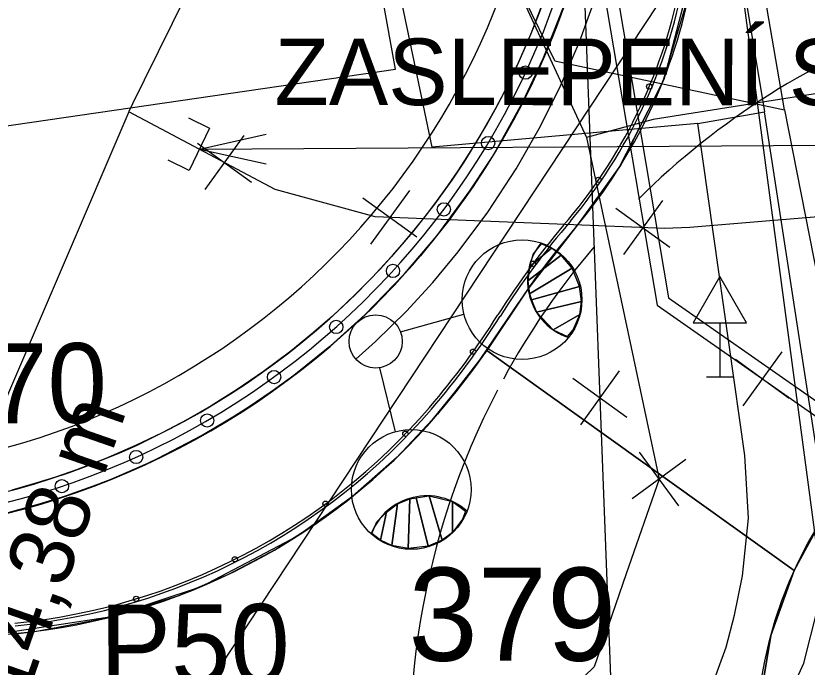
# Model space of a CAD drawing. Extents: x -643342 to -638635, y -1201752 to -1189948.
# Drawn here: x -639514.49 to -639499.63, y -1192712.17 to -1192699.92 of the extents above; entities that cross this region are included whole.
import ezdxf

# ---------------------------------------------------------------- set-up
doc = ezdxf.new("R2010")
doc.units = 0
for name, color, linetype in [('-zbytky_kruháče', 7, 'Continuous'), ('42', 7, 'Continuous'), ('IS_PLYN_STL', 7, 'Continuous'), ('IS_TELEF_MISTNI_ZAMERENO', 7, 'Continuous'), ('IS_VODOVOD_VAS', 7, 'Continuous'), ('IS_VODOVOD_ZRUSENY', 7, 'Continuous'), ('K-HRANICE_KN', 7, 'Continuous'), ('K-ČÍSLA_PARCEL', 7, 'Continuous'), ('kanalizace_dešťová_stávající', 7, 'Continuous'), ('N-CHODNIK', 7, 'Continuous'), ('N-KAN_DEST_TRASA-NÁVRH', 7, 'Continuous'), ('N-OBVOD STAVBY 06', 7, 'Continuous'), ('N-oploceni', 7, 'Continuous'), ('N-rusene_vedeni', 7, 'Continuous'), ('N-SILNICE', 7, 'Continuous'), ('N-SRAFY_PLOCHY', 7, 'Continuous'), ('N-vo', 7, 'Continuous'), ('N-ZDI', 7, 'Continuous'), ('N-úprava plochu u obecního úřadu', 7, 'Continuous'), ('RWE_STL_RADY', 7, 'Continuous'), ('tomaštík - Džuganovi - Vrstva 36', 7, 'Continuous'), ('Vrstva 13', 7, 'Continuous'), ('Vrstva 42', 7, 'Continuous'), ('Vrstva 46', 7, 'Continuous'), ('Z-hrany_a_čáry', 7, 'Continuous'), ('Z-značky', 7, 'Continuous')]:
    doc.layers.add(name, color=color, linetype=linetype)

# ---------------------------------------------------------------- blocks, each defined once
blk = doc.blocks.new('SZASL')
at = {"layer": 'Vrstva 13'}
for p, q in [((-44.1, 44.1), (0, 44.1)), ((0, 44.1), (0, -44.1)), ((0, -44.1), (-44.1, -44.1))]:
    blk.add_line(p, q, dxfattribs=at)
blk = doc.blocks.new('SLOUPEK')
blk.add_circle((0, 0), 0.125)
blk = doc.blocks.new('zs')
at = {"layer": 'N-oploceni'}
blk.add_circle((0, 0), 0.05, dxfattribs=at)

msp = doc.modelspace()

# ---------------------------------------------------------------- linework, layer by layer
at = {"layer": '-zbytky_kruháče'}
for start, end in [(109.782, 134.7666), (139.621, 151.5281), (152.4602, 296.3322)]:
    msp.add_arc((-639492.588, -1192713.663), 14.5, start, end, dxfattribs=at)
at = {"layer": '42'}
msp.add_line((-639511.045, -1192702.433), (-639465.369, -1192702.13), dxfattribs=at)
at = {"layer": 'IS_PLYN_STL'}
for points in [[(-639512.56, -1192644.42), (-639512.26, -1192649.59), (-639511.32, -1192655.27), (-639510.7, -1192659.4), (-639510.65, -1192659.78), (-639509.28, -1192668.1), (-639508.19, -1192675.05), (-639508.14, -1192676.33), (-639508.13, -1192676.63), (-639507.89, -1192680.08), (-639507.71, -1192681.06), (-639506.97, -1192684.98), (-639506.93, -1192686.16), (-639507.42, -1192689.07), (-639507.53, -1192689.98), (-639508.21, -1192692.47), (-639508.65, -1192694.18), (-639512.08, -1192701.13)], [(-639512.08, -1192701.13), (-639512.3, -1192701.58), (-639512.37, -1192701.72), (-639512.37, -1192701.73)], [(-639512.37, -1192701.73), (-639516.15, -1192710.55), (-639516.26, -1192710.8), (-639516.59, -1192711.63), (-639520.92, -1192722.11)], [(-639470.24, -1192716.66), (-639471.45, -1192716.75), (-639474.85, -1192717.23), (-639477.45, -1192717.59), (-639486.49, -1192709.11), (-639487.46, -1192707.33), (-639488.82, -1192705.38), (-639489.11, -1192702.85), (-639489.56, -1192702.88), (-639501.83, -1192703.9), (-639502.31, -1192703.92), (-639507.74, -1192703.7), (-639509.62, -1192703.19), (-639512.37, -1192701.73)]]:
    msp.add_lwpolyline(points, dxfattribs=at)
at = {"layer": 'IS_TELEF_MISTNI_ZAMERENO'}
for p, q in [((-639505.51, -1192698.45), (-639503.77, -1192702.21)), ((-639491.24, -1192700.09), (-639502.52, -1192701.87)), ((-639491.24, -1192700.09), (-639502.52, -1192701.87)), ((-639502.52, -1192701.87), (-639503.77, -1192702.21)), ((-639503.77, -1192702.21), (-639502.41, -1192708.63)), ((-639502.41, -1192708.63), (-639503.03, -1192710.41)), ((-639503.03, -1192710.41), (-639503.63, -1192712.16)), ((-639503.63, -1192712.16), (-639504.73, -1192713.21))]:
    msp.add_line(p, q, dxfattribs=at)
at = {"layer": 'IS_VODOVOD_VAS'}
for points in [[(-639513.05, -1192632.38), (-639511.6, -1192653.11), (-639509.94, -1192661.802), (-639509.17, -1192665.92), (-639508.128, -1192674.317), (-639507.037, -1192678.26), (-639504.087, -1192695.682), (-639502.448, -1192705.362), (-639494.166, -1192711.159), (-639494.54, -1192716.007), (-639495.94, -1192729.045), (-639496.55, -1192731.72), (-639496.617, -1192732.012), (-639498.895, -1192762.442), (-639502.42, -1192797.68), (-639508.622, -1192858.606)], [(-639503.85, -1192695.64), (-639502.23, -1192705.222), (-639493.917, -1192711.041), (-639494.301, -1192716.029), (-639495.801, -1192729.991)]]:
    msp.add_lwpolyline(points, dxfattribs=at)
at = {"layer": 'IS_VODOVOD_ZRUSENY'}
msp.add_lwpolyline([(-639515.23, -1192614.43), (-639514.98, -1192614.84), (-639507.86, -1192661.34), (-639506.03, -1192670.84), (-639505.88, -1192671.62), (-639500.98, -1192698.45), (-639496.78, -1192729.96)], dxfattribs=at)
at = {"layer": 'K-HRANICE_KN'}
for p, q in [((-639500.054, -1192701.689), (-639514.492, -1192617.042)), ((-639500.054, -1192701.689), (-639514.492, -1192617.042)), ((-639504.367, -1192700.769), (-639509.13, -1192691.04)), ((-639507.364, -1192700.925), (-639509.13, -1192691.04)), ((-639504.367, -1192700.769), (-639509.13, -1192691.04)), ((-639507.364, -1192700.925), (-639509.13, -1192691.04)), ((-639504.367, -1192700.769), (-639500.054, -1192701.689)), ((-639504.367, -1192700.769), (-639500.054, -1192701.689)), ((-639517.942, -1192702.472), (-639507.364, -1192700.925)), ((-639517.942, -1192702.472), (-639507.364, -1192700.925)), ((-639500.054, -1192701.689), (-639498.299, -1192710.648)), ((-639500.054, -1192701.689), (-639498.299, -1192710.648))]:
    msp.add_line(p, q, dxfattribs=at)
at = {"layer": 'kanalizace_dešťová_stávající'}
msp.add_line((-639504.48, -1192681.98), (-639503.2, -1192715.57), dxfattribs=at)
at = {"layer": 'N-CHODNIK'}
msp.add_lwpolyline([(-639515.106, -1192709.38), (-639514.329, -1192709.187), (-639513.468, -1192708.921), (-639512.701, -1192708.635), (-639512.036, -1192708.347), (-639511.296, -1192707.98), (-639510.616, -1192707.595), (-639509.882, -1192707.126), (-639509.227, -1192706.653), (-639508.714, -1192706.244), (-639508.076, -1192705.679), (-639507.517, -1192705.127), (-639507.038, -1192704.606), (-639506.576, -1192704.051), (-639506.038, -1192703.328), (-639505.523, -1192702.541), (-639505.08, -1192701.762), (-639504.715, -1192701.028), (-639504.372, -1192700.227), (-639504.087, -1192699.438)], dxfattribs=at)
at = {"layer": 'N-KAN_DEST_TRASA-NÁVRH'}
msp.add_lwpolyline([(-639583.962, -1192528.01), (-639550.452, -1192564.184), (-639529.583, -1192588.026), (-639514.491, -1192612.048), (-639507.737, -1192644.326), (-639498.832, -1192694.254), (-639511.439, -1192713.331), (-639516.613, -1192716.507), (-639553.938, -1192703.739), (-639570.485, -1192701.616), (-639578.687, -1192703.18)], dxfattribs=at)
at = {"layer": 'N-OBVOD STAVBY 06'}
msp.add_arc((-639518.329, -1192694.73), 13.8, 270.2555, 355.9918, dxfattribs=at)
at = {"layer": 'N-oploceni'}
for centre, radius, start, end in [((-639518.329, -1192694.73), 14.8, 270.2555, 355.9918), ((-639511.632, -1192697.467), 9.8, 320.1186, 349.4986), ((-639492.585, -1192713.656), 15.198, 139.329, 147.7483), ((-639518.037, -1192697.572), 14.91, 319.362, 327.6716), ((-639515.675, -1192699.595), 11.8, 275.6507, 319.3448)]:
    msp.add_arc(centre, radius, start, end, dxfattribs=at)
at = {"layer": 'N-rusene_vedeni'}
for p, q in [((-639510.209, -1192702.176), (-639510.941, -1192703.19)), ((-639511.082, -1192702.317), (-639510.068, -1192703.049)), ((-639507.101, -1192703.204), (-639507.833, -1192704.218)), ((-639507.974, -1192703.345), (-639506.96, -1192704.077)), ((-639502.348, -1192703.397), (-639503.079, -1192704.41)), ((-639503.22, -1192703.538), (-639502.207, -1192704.269)), ((-639500.105, -1192706.239), (-639500.836, -1192707.253)), ((-639500.977, -1192706.38), (-639499.964, -1192707.112)), ((-639503.157, -1192706.596), (-639503.888, -1192707.609)), ((-639504.029, -1192706.737), (-639503.016, -1192707.469)), ((-639502.041, -1192709.135), (-639502.779, -1192708.125)), ((-639501.905, -1192708.261), (-639502.915, -1192708.999))]:
    msp.add_line(p, q, dxfattribs=at)
at = {"layer": 'N-SILNICE'}
msp.add_circle((-639492.588, -1192713.663), 8, dxfattribs=at)
for centre, radius, start, end in [((-639511.632, -1192697.467), 9.85, 320.1186, 349.4986), ((-639511.632, -1192697.467), 10, 320.1186, 349.4986), ((-639492.583, -1192713.657), 15.15, 139.3194, 147.7483), ((-639492.583, -1192713.657), 15, 139.3194, 147.7483), ((-639517.951, -1192697.64), 14.85, 319.3448, 327.7166), ((-639517.951, -1192697.64), 15, 319.3448, 327.7166), ((-639515.675, -1192699.595), 11.85, 275.6507, 319.3448), ((-639515.675, -1192699.595), 12, 275.6507, 319.3448)]:
    msp.add_arc(centre, radius, start, end, dxfattribs=at)
at = {"layer": 'N-SRAFY_PLOCHY'}
for p, q in [((-639501.716, -1192698.816), (-639502.323, -1192701.118)), ((-639504.067, -1192699.377), (-639504.342, -1192700.149)), ((-639502.342, -1192701.168), (-639501.841, -1192699.498)), ((-639504.584, -1192699.653), (-639504.817, -1192700.26)), ((-639504.586, -1192700.725), (-639504.209, -1192699.776)), ((-639504.817, -1192700.26), (-639505.068, -1192700.837)), ((-639504.342, -1192700.149), (-639504.678, -1192700.947)), ((-639504.97, -1192701.542), (-639504.586, -1192700.725)), ((-639505.068, -1192700.837), (-639505.266, -1192701.25)), ((-639504.678, -1192700.947), (-639505.05, -1192701.707)), ((-639503.157, -1192702.774), (-639502.342, -1192701.168)), ((-639502.323, -1192701.118), (-639503.134, -1192702.737)), ((-639505.266, -1192701.25), (-639505.48, -1192701.664)), ((-639505.523, -1192702.541), (-639504.97, -1192701.542)), ((-639505.48, -1192701.664), (-639505.771, -1192702.176)), ((-639505.05, -1192701.707), (-639505.524, -1192702.543)), ((-639505.771, -1192702.176), (-639506.079, -1192702.674)), ((-639506.079, -1192702.674), (-639506.305, -1192703.011)), ((-639505.944, -1192703.185), (-639505.523, -1192702.541)), ((-639505.524, -1192702.543), (-639505.903, -1192703.133)), ((-639503.134, -1192702.737), (-639503.959, -1192703.879)), ((-639503.861, -1192703.76), (-639503.157, -1192702.774)), ((-639506.305, -1192703.011), (-639506.63, -1192703.465)), ((-639506.576, -1192704.051), (-639505.944, -1192703.185)), ((-639505.903, -1192703.133), (-639506.361, -1192703.773)), ((-639506.63, -1192703.465), (-639507.041, -1192703.99)), ((-639506.361, -1192703.773), (-639506.892, -1192704.436)), ((-639504.695, -1192704.807), (-639503.861, -1192703.76)), ((-639507.041, -1192703.99), (-639507.434, -1192704.449)), ((-639503.959, -1192703.879), (-639504.875, -1192705.059)), ((-639507.19, -1192704.771), (-639506.576, -1192704.051)), ((-639507.434, -1192704.449), (-639507.79, -1192704.834)), ((-639506.892, -1192704.436), (-639507.38, -1192704.983)), ((-639507.79, -1192704.834), (-639508.13, -1192705.177)), ((-639507.936, -1192705.541), (-639507.19, -1192704.771)), ((-639505.139, -1192705.449), (-639504.695, -1192704.807)), ((-639507.38, -1192704.983), (-639508.038, -1192705.643)), ((-639508.13, -1192705.177), (-639508.551, -1192705.572)), ((-639504.875, -1192705.059), (-639505.644, -1192706.215)), ((-639505.888, -1192706.556), (-639505.139, -1192705.449)), ((-639508.551, -1192705.572), (-639508.936, -1192705.907)), ((-639508.714, -1192706.244), (-639507.936, -1192705.541)), ((-639508.038, -1192705.643), (-639508.592, -1192706.14)), ((-639508.936, -1192705.907), (-639509.329, -1192706.226)), ((-639509.329, -1192706.226), (-639509.842, -1192706.61)), ((-639509.442, -1192706.808), (-639508.714, -1192706.244)), ((-639508.592, -1192706.14), (-639509.27, -1192706.686)), ((-639505.644, -1192706.215), (-639506.571, -1192707.413)), ((-639505.644, -1192706.215), (-639499.869, -1192710.347)), ((-639499.869, -1192710.347), (-639505.644, -1192706.215)), ((-639509.842, -1192706.61), (-639510.333, -1192706.946)), ((-639509.27, -1192706.686), (-639509.906, -1192707.142)), ((-639506.729, -1192707.593), (-639505.888, -1192706.556)), ((-639510.249, -1192707.36), (-639509.442, -1192706.808)), ((-639510.333, -1192706.946), (-639510.823, -1192707.253)), ((-639510.823, -1192707.253), (-639511.28, -1192707.516)), ((-639509.906, -1192707.142), (-639510.591, -1192707.581)), ((-639511.004, -1192707.814), (-639510.249, -1192707.36)), ((-639506.571, -1192707.413), (-639507.33, -1192708.218)), ((-639511.28, -1192707.516), (-639511.757, -1192707.767)), ((-639510.591, -1192707.581), (-639511.225, -1192707.942)), ((-639507.387, -1192708.273), (-639506.729, -1192707.593)), ((-639511.757, -1192707.767), (-639512.243, -1192708.002)), ((-639511.95, -1192708.304), (-639511.004, -1192707.814)), ((-639512.243, -1192708.002), (-639512.802, -1192708.244)), ((-639511.225, -1192707.942), (-639511.922, -1192708.293)), ((-639512.802, -1192708.244), (-639513.352, -1192708.456)), ((-639512.79, -1192708.668), (-639511.95, -1192708.304)), ((-639511.922, -1192708.293), (-639512.755, -1192708.656)), ((-639508.278, -1192709.044), (-639507.387, -1192708.273)), ((-639507.33, -1192708.218), (-639508.168, -1192708.956)), ((-639513.352, -1192708.456), (-639513.751, -1192708.594)), ((-639513.751, -1192708.594), (-639514.159, -1192708.722)), ((-639514.159, -1192708.722), (-639514.571, -1192708.838)), ((-639513.719, -1192708.999), (-639512.79, -1192708.668)), ((-639512.755, -1192708.656), (-639513.477, -1192708.924)), ((-639514.895, -1192709.328), (-639513.719, -1192708.999)), ((-639513.477, -1192708.924), (-639514.476, -1192709.227)), ((-639508.168, -1192708.956), (-639509.205, -1192709.701)), ((-639508.843, -1192709.46), (-639508.278, -1192709.044)), ((-639514.476, -1192709.227), (-639515.6, -1192709.48)), ((-639509.617, -1192709.953), (-639508.843, -1192709.46)), ((-639499.869, -1192710.347), (-639499.36, -1192709.404)), ((-639509.205, -1192709.701), (-639511.014, -1192710.653)), ((-639510.49, -1192710.417), (-639509.617, -1192709.953)), ((-639500.31, -1192711.571), (-639499.869, -1192710.347)), ((-639511.427, -1192710.818), (-639510.49, -1192710.417)), ((-639511.014, -1192710.653), (-639512.733, -1192711.228)), ((-639512.777, -1192711.24), (-639511.427, -1192710.818)), ((-639512.733, -1192711.228), (-639515.228, -1192711.602)), ((-639514.136, -1192711.496), (-639512.777, -1192711.24)), ((-639515.461, -1192711.62), (-639514.136, -1192711.496)), ((-639500.57, -1192713.12), (-639500.31, -1192711.571))]:
    msp.add_line(p, q, dxfattribs=at)
msp.add_lwpolyline([(-639499.36, -1192709.404), (-639499.869, -1192710.347), (-639500.31, -1192711.571), (-639500.57, -1192713.12), (-639500.578, -1192714.067), (-639500.433, -1192715.231), (-639500.147, -1192716.285), (-639499.752, -1192717.224), (-639499.203, -1192718.163)], dxfattribs=at)
at = {"layer": 'N-vo'}
for p, q in [((-639507.267, -1192705.866), (-639506.075, -1192705.531)), ((-639507.66, -1192706.539), (-639507.366, -1192707.742))]:
    msp.add_line(p, q, dxfattribs=at)
msp.add_lwpolyline([(-639508.109, -1192706.375), (-639507.734, -1192706.044), (-639507.157, -1192705.475), (-639506.662, -1192704.935), (-639506.183, -1192704.36), (-639505.628, -1192703.614), (-639505.097, -1192702.802), (-639504.638, -1192701.997), (-639504.261, -1192701.237), (-639503.907, -1192700.41), (-639503.612, -1192699.594), (-639503.33, -1192698.641), (-639503.082, -1192697.518), (-639502.921, -1192696.417), (-639502.841, -1192695.404), (-639502.805, -1192694.473), (-639502.803, -1192693.26), (-639502.846, -1192692.155), (-639502.942, -1192690.954), (-639503.007, -1192690.373)], dxfattribs=at)
for points in [[(-639504.433, -1192704.288), (-639504.843, -1192704.644), (-639504.876, -1192704.903), (-639504.246, -1192704.422)], [(-639504.625, -1192704.209), (-639504.773, -1192704.398), (-639504.843, -1192704.644), (-639504.433, -1192704.288)], [(-639504.246, -1192704.422), (-639504.876, -1192704.903), (-639504.842, -1192705.152), (-639504.041, -1192704.664)], [(-639504.041, -1192704.664), (-639504.842, -1192705.152), (-639504.803, -1192705.263), (-639503.902, -1192705.013)], [(-639503.902, -1192705.013), (-639504.803, -1192705.263), (-639504.71, -1192705.495), (-639503.869, -1192705.296)], [(-639503.869, -1192705.296), (-639504.71, -1192705.495), (-639504.402, -1192705.823), (-639503.899, -1192705.535)], [(-639503.899, -1192705.535), (-639504.402, -1192705.823), (-639504.127, -1192705.95), (-639504.024, -1192705.823)], [(-639507.432, -1192709.879), (-639507.322, -1192709.094), (-639507.089, -1192709.001), (-639507.121, -1192709.938)], [(-639507.121, -1192709.938), (-639507.089, -1192709.001), (-639506.974, -1192708.981), (-639506.749, -1192709.889)], [(-639506.749, -1192709.889), (-639506.974, -1192708.981), (-639506.726, -1192708.947), (-639506.486, -1192709.778)], [(-639506.486, -1192709.778), (-639506.726, -1192708.947), (-639506.288, -1192709.055), (-639506.292, -1192709.634)], [(-639506.292, -1192709.634), (-639506.288, -1192709.055), (-639506.043, -1192709.232), (-639506.102, -1192709.384)], [(-639507.641, -1192709.782), (-639507.533, -1192709.251), (-639507.322, -1192709.094), (-639507.432, -1192709.879)], [(-639507.804, -1192709.654), (-639507.712, -1192709.432), (-639507.533, -1192709.251), (-639507.641, -1192709.782)]]:
    msp.add_lwpolyline(points, close=True, dxfattribs=at)
for centre, radius in [((-639504.983, -1192705.259), 1.125), ((-639507.734, -1192706.044), 0.5), ((-639507.065, -1192708.826), 1.125)]:
    msp.add_circle(centre, radius, dxfattribs=at)
for centre, start, end in [((-639503.755, -1192704.904), 140.7644, 251.4767), ((-639506.771, -1192710.07), 47.9657, 158.678)]:
    msp.add_arc(centre, 1.125, start, end, dxfattribs=at)
at = {"layer": 'N-ZDI'}
for radius in [14.6, 15]:
    msp.add_arc((-639518.329, -1192694.73), radius, 270.2555, 355.9918, dxfattribs=at)
at = {"layer": 'Vrstva 42'}
for q in [(-639509.792, -1192702.148), (-639509.789, -1192702.705)]:
    msp.add_line((-639511.045, -1192702.433), q, dxfattribs=at)
at = {"layer": 'Z-hrany_a_čáry'}
for p, q in [((-639502.81, -1192687.42), (-639500.43, -1192701.73)), ((-639506.67, -1192702.39), (-639508.01, -1192696.02)), ((-639501.68, -1192701.95), (-639500.43, -1192701.73)), ((-639499.34, -1192708.8), (-639500.43, -1192701.73)), ((-639501.68, -1192701.95), (-639506.67, -1192702.39)), ((-639500.8, -1192708.19), (-639501.68, -1192701.95)), ((-639500.732, -1192709.365), (-639500.8, -1192708.19)), ((-639500.845, -1192710.447), (-639500.732, -1192709.365)), ((-639500.99, -1192711.19), (-639500.845, -1192710.447)), ((-639499.69, -1192712.09), (-639499.432, -1192711.074)), ((-639501.151, -1192711.787), (-639500.99, -1192711.19)), ((-639501.41, -1192712.51), (-639501.151, -1192711.787)), ((-639500.176, -1192713.136), (-639499.69, -1192712.09))]:
    msp.add_line(p, q, dxfattribs=at)
at = {"layer": 'Z-značky'}
for p, q in [((-639501.27, -1192704.826), (-639501.77, -1192705.692)), ((-639500.77, -1192705.692), (-639501.27, -1192704.826)), ((-639501.77, -1192705.692), (-639500.77, -1192705.692)), ((-639501.27, -1192705.692), (-639501.27, -1192706.71)), ((-639501.52, -1192706.71), (-639501.02, -1192706.71))]:
    msp.add_line(p, q, dxfattribs=at)

# ---------------------------------------------------------------- block references
at = {"layer": 'N-oploceni'}
for p, rotation in [((-639504.918, -1192700.991), 64.97682595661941), ((-639505.621, -1192702.315), 59.169821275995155), ((-639506.453, -1192703.562), 53.36281659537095), ((-639507.408, -1192704.719), 47.55581191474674), ((-639508.474, -1192705.772), 41.74880723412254), ((-639509.642, -1192706.713), 35.94180255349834), ((-639510.899, -1192707.53), 30.13479787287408), ((-639512.232, -1192708.216), 24.327793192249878), ((-639513.628, -1192708.764), 18.520788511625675)]:
    msp.add_blockref('SLOUPEK', p, dxfattribs=dict(at, rotation=rotation))
at = {"layer": 'N-úprava plochu u obecního úřadu'}
for p, rotation in [((-639502.593, -1192701.253), 67.2732344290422), ((-639503.548, -1192703.006), 55.58021827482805), ((-639504.778, -1192704.583), 53.34709005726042), ((-639505.903, -1192706.236), 54.472427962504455), ((-639507.174, -1192707.778), 46.091048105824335), ((-639508.676, -1192709.095), 36.37989786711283), ((-639510.379, -1192710.139), 26.66874762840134), ((-639512.233, -1192710.882), 16.957597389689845), ((-639514.186, -1192711.3), 7.246447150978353)]:
    msp.add_blockref('zs', p, dxfattribs=dict(at, rotation=rotation))
at = {"layer": 'RWE_STL_RADY', "xscale": 0.009999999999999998, "yscale": 0.01, "rotation": -25.86358812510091}
msp.add_blockref('SZASL', (-639511.045, -1192702.433), dxfattribs=at)

# ---------------------------------------------------------------- texts
at = {"layer": 'K-ČÍSLA_PARCEL'}
msp.add_text('379', height=1.75, dxfattribs=at).set_placement((-639507.118, -1192712.045))
msp.add_text('379', height=1.75, dxfattribs=at).set_placement((-639507.118, -1192712.045))
at = {"layer": 'RWE_STL_RADY'}
msp.add_text('STLPE 110 - 14,38 m', height=1.2, rotation=70.8102, dxfattribs=at).set_placement((-639517.48, -1192721.918))
at = {"layer": 'tomaštík - Džuganovi - Vrstva 36'}
msp.add_text('ZASLEPENÍ STÁVAJÍCÍHO PLYNOVODU PE 110', height=1.25, rotation=359.9647, dxfattribs=at).set_placement((-639509.633, -1192701.6))
at = {"layer": 'Vrstva 46'}
for s, p in [('L70', (-639516.125, -1192707.59)), ('P50', (-639512.913, -1192712.494))]:
    msp.add_text(s, height=1.5, rotation=0.301, dxfattribs=at).set_placement(p)

doc.saveas('drawing.dxf')
